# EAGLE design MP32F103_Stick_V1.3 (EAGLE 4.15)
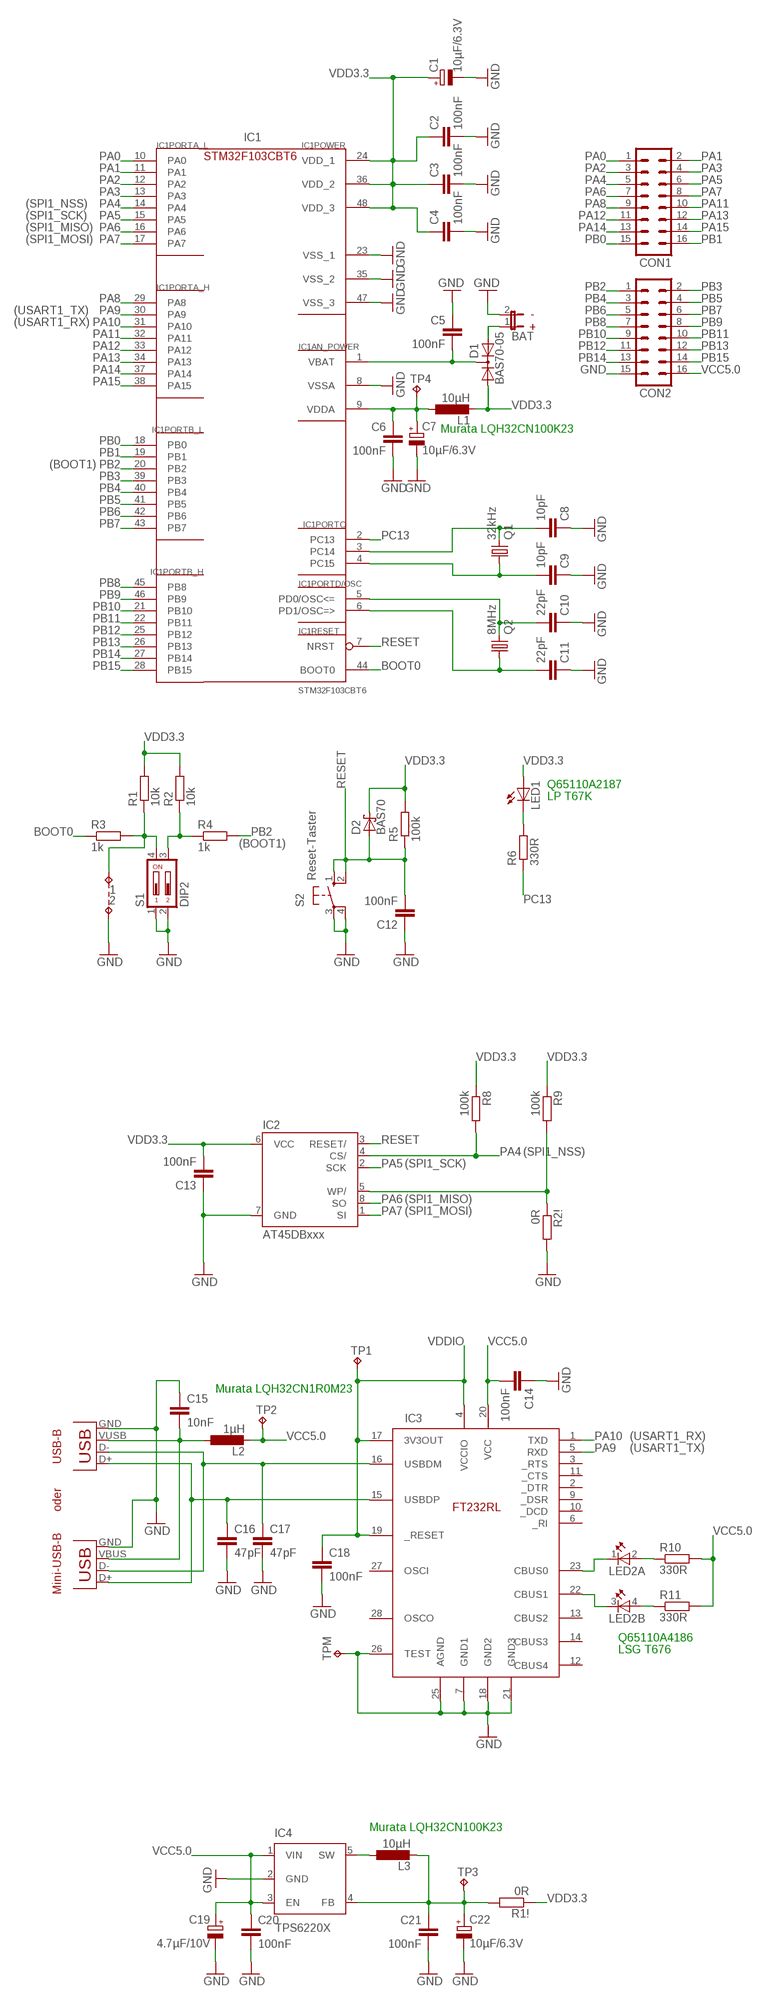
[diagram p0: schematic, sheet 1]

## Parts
1  TP09SQ  [TP09SQ]
2  TP09SQ  [TP09SQ]
BAT  JP1EMP  [JP1_MP]
C1  10µF/6.3V  CPOL-EUA/3216-18R  [A/3216-18R]
C2  100nF  C-EUC0805  [C0805]
C3  100nF  C-EUC0805  [C0805]
C4  100nF  C-EUC0805  [C0805]
C5  100nF  C-EUC0805  [C0805]
C6  100nF  C-EUC0805  [C0805]
C7  10µF/6.3V  CPOL-EUA/3216-18R  [A/3216-18R]
C8  10pF  C-EUC0805K  [C0805K]
C9  10pF  C-EUC0805K  [C0805K]
C10  22pF  C-EUC0805K  [C0805K]
C11  22pF  C-EUC0805K  [C0805K]
C12  100nF  C-EUC0805K  [C0805K]
C13  100nF  C-EUC0805K  [C0805K]
C14  100nF  C-EUC0805K  [C0805K]
C15  10nF  C-EUC0805K  [C0805K]
C16  47pF  C-EUC0805K  [C0805K]
C17  47pF  C-EUC0805K  [C0805K]
C18  100nF  C-EUC0805K  [C0805K]
C19  4.7µF/10V  CPOL-EUA/3216-18R  [A/3216-18R]
C20  100nF  C-EUC0805  [C0805]
C21  100nF  C-EUC0805  [C0805]
C22  10µF/6.3V  CPOL-EUA/3216-18R  [A/3216-18R]
CON1  ML16  [ML16]
CON2  ML16  [ML16]
D1  BAS70-05  [SOT23]
D2  BAS70  [SOT23]
IC1  STM32F103CBT6  STM32F10XCXT6  [TQFP48]
IC2  AT45DBxxx  AT45DB  [SOIC8]
IC3  FT232RL  [SSOP28DB]
IC4  TPS6220X  [SOT23-5L]
L1  10µH  L-EUL1210  [R1210]
L2  1µH  L-EUL1210  [R1210]
L3  10µH  L-EUL1210  [R1210]
LED1  LEDP-LCC-2_MPI  [P-LCC-2-MPI]
LED2  TOPLED-2-MPI  [P-LCC-4-2-MPI]
Q1  32kHz  CRYTALTC26H  [TC26H]
Q2  8MHz  CRYTALHC49U-V  [HC49U-V]
R1  10k  R-EU_R0805  [R0805]
R1!  0R  R-EU_R0805  [R0805]
R2  10k  R-EU_R0805  [R0805]
R2!  0R  R-EU_R0805  [R0805]
R3  1k  R-EU_R0805  [R0805]
R4  1k  R-EU_R0805  [R0805]
R5  100k  R-EU_R0805  [R0805]
R6  330R  R-EU_R0805  [R0805]
R8  100k  R-EU_R0805  [R0805]
R9  100k  R-EU_R0805  [R0805]
R10  330R  R-EU_R0805  [R0805]
R11  330R  R-EU_R0805  [R0805]
S1  DIP2  DS02  [DS-02]
S2  Reset-Taster  10-XX  [B3F-10XX]
TP1  TP09SQ  [TP09SQ]
TP2  TP09SQ  [TP09SQ]
TP3  TP09SQ  [TP09SQ]
TP4  TP09SQ  [TP09SQ]
TPM  TP09SQ  [TP09SQ]
USB1  USB-B-S  [USB-B-SMT]
USB2  USB-MB-S2  [USB-MP-S2]

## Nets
3V3: C21.1 C22.+ IC4.4(FB) L3.2 R1!.2 TP3.TP
BOOT0: IC1.44(RESET:BOOT0) R3.1
D+: C16.1 IC3.15(USBDP) USB1.D+ USB2.D+
D-: C17.1 IC3.16(USBDM) USB1.D- USB2.D-
GND: 2.TP BAT.2 C1.- C2.2 C3.2 C4.2 C5.1 C6.2 C7.- C8.1 C9.1 C10.1 C11.1 C12.1 C13.1 C14.1 C15.1 C16.2 C17.2 C18.2 C19.- C20.2 C21.2 C22.- CON2.15 IC1.8(AN_POWER:VSSA) IC1.23(POWER:VSS_1) IC1.35(POWER:VSS_2) IC1.47(POWER:VSS_3) IC2.7(GND) IC3.7(GND1) IC3.18(GND2) IC3.21(GND3) IC3.25(AGND) IC3.26(TEST) IC4.2(GND) R2!.2 S1.1 S1.2 S2.3(P) S2.4(P1) TPM.TP USB1.GND USB2.GND
N$1: IC4.5(SW) L3.1
N$2: IC3.23(CBUS0) LED2.1(A:C)
N$3: IC3.22(CBUS1) LED2.3(B:C)
N$4: LED2.2(A:A) R10.1
N$5: LED2.4(B:A) R11.1
N$8: BAT.1 D1.2(A2)
N$9: LED1.C R6.2
N$10: 1.TP R1.1 R3.2 S1.4
N$11: R2.1 R4.1 S1.3
N$16: C9.2 IC1.4(PORTC:PC15) Q1.1
N$18: C10.2 IC1.5(PORTD/OSC:PD0/OSC<=) Q2.2
N$19: C11.2 IC1.6(PORTD/OSC:PD1/OSC=>) Q2.1
N$20: C8.2 IC1.3(PORTC:PC14) Q1.2
PA0: CON1.1 IC1.10(PORTA_L:PA0)
PA1: CON1.2 IC1.11(PORTA_L:PA1)
PA2: CON1.3 IC1.12(PORTA_L:PA2)
PA3: CON1.4 IC1.13(PORTA_L:PA3)
PA4: CON1.5 IC1.14(PORTA_L:PA4) IC2.4(CS/) R8.2
PA5: CON1.6 IC1.15(PORTA_L:PA5) IC2.2(SCK)
PA6: CON1.7 IC1.16(PORTA_L:PA6) IC2.8(SO)
PA7: CON1.8 IC1.17(PORTA_L:PA7) IC2.1(SI)
PA8: CON1.9 IC1.29(PORTA_H:PA8)
PA9: IC1.30(PORTA_H:PA9) IC3.5(RXD)
PA10: IC1.31(PORTA_H:PA10) IC3.1(TXD)
PA11: CON1.10 IC1.32(PORTA_H:PA11)
PA12: CON1.11 IC1.33(PORTA_H:PA12)
PA13: CON1.12 IC1.34(PORTA_H:PA13)
PA14: CON1.13 IC1.37(PORTA_H:PA14)
PA15: CON1.14 IC1.38(PORTA_H:PA15)
PB0: CON1.15 IC1.18(PORTB_L:PB0)
PB1: CON1.16 IC1.19(PORTB_L:PB1)
PB2: CON2.1 IC1.20(PORTB_L:PB2) R4.2
PB3: CON2.2 IC1.39(PORTB_L:PB3)
PB4: CON2.3 IC1.40(PORTB_L:PB4)
PB5: CON2.4 IC1.41(PORTB_L:PB5)
PB6: CON2.5 IC1.42(PORTB_L:PB6)
PB7: CON2.6 IC1.43(PORTB_L:PB7)
PB8: CON2.7 IC1.45(PORTB_H:PB8)
PB9: CON2.8 IC1.46(PORTB_H:PB9)
PB10: CON2.9 IC1.21(PORTB_H:PB10)
PB11: CON2.10 IC1.22(PORTB_H:PB11)
PB12: CON2.11 IC1.25(PORTB_H:PB12)
PB13: CON2.12 IC1.26(PORTB_H:PB13)
PB14: CON2.13 IC1.27(PORTB_H:PB14)
PB15: CON2.14 IC1.28(PORTB_H:PB15)
PC13: IC1.2(PORTC:PC13) R6.1
RESET: C12.2 D2.1(A) IC1.7(RESET:NRST) IC2.3(RESET/) R5.1 S2.1(S) S2.2(S1)
VBAT: C5.2 D1.3(C) IC1.1(AN_POWER:VBAT)
VBUS: C15.2 L2.1 USB1.VUSB(VBUS) USB2.VBUS
VCC5.0: C14.2 C19.+ C20.1 CON2.16 IC3.20(VCC) IC4.1(VIN) IC4.3(EN) L2.2 R10.2 R11.2 TP2.TP
VDD3.3: C1.+ C2.1 C3.1 C4.1 C13.2 D1.1(A1) D2.3(C) IC1.24(POWER:VDD_1) IC1.36(POWER:VDD_2) IC1.48(POWER:VDD_3) IC2.6(VCC) L1.2 LED1.A R1!.1 R1.2 R2.2 R5.2 R8.1 R9.1
VDDA: C6.1 C7.+ IC1.9(AN_POWER:VDDA) L1.1 TP4.TP
VDDIO: C18.1 IC3.4(VCCIO) IC3.17(3V3OUT) IC3.19(_RESET) TP1.TP
WP/: IC2.5(WP/) R2!.1 R9.2
Unconnected: IC3.2(_DTR) IC3.3(_RTS) IC3.6(_RI) IC3.9(_DSR) IC3.10(_DCD) IC3.11(_CTS) IC3.12(CBUS4) IC3.13(CBUS2) IC3.14(CBUS3) IC3.27(OSCI) IC3.28(OSCO)

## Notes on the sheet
- IC1
- STM32F103CBT6
- (SPI1_NSS)
- (SPI1_SCK)
- (SPI1_MISO)
- (SPI1_MOSI)
- (USART1_TX)
- -
- (USART1_RX)
- +
- Murata LQH32CN100K23
- (BOOT1)
- Q65110A2187
- LP T67K
- (BOOT1)
- (SPI1_NSS)
- (SPI1_SCK)
- (SPI1_MISO)
- (SPI1_MOSI)
- Murata LQH32CN1R0M23
- (USART1_RX)
- (USART1_TX)
- USB-B
- oder | FT232RL
- Mini-USB-B
- Q65110A4186
- LSG T676
- Murata LQH32CN100K23

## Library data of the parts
1 2 TP1-TP4 TPM = testpad:TP09SQ: TEST PIN
BAT = jumper:JP1E: JUMPER
C1 C7 C19 C22 = rcl:CPOL-EU: POLARIZED CAPACITOR, European symbol
C2-C6 C8-C18 C20 C21 = rcl:C-EU: CAPACITOR, European symbol
CON1 CON2 = con-harting-ml:ML16: HARTING
D1 = diode:BAS70-05: Silicon Schottky Diodes General-purpose diode for high-speed switching
D2 = diode:BAS70: Silicon Schottky Diodes
IC1 = stm32:STM32F10XCXT6: ST STM32F101/103 48pin LQFP
IC2 = atmel:AT45DB*
IC3 = ftdichip:FT232RL: USB UART 4th Generation USB UART (USB <-> Serial) Controller
IC4 = texas_MPi:TPS6220X
L1-L3 = rcl:L-EU: INDUCTOR, European symbol
LED1 = led:LED: LED
LED2 = led:TOPLED-2-: Multi TOPLED® (two color) LG T672, LP T672 LSY T67B LSW T67C LSY T675 LSY T676 LSG T677 LSG T770 Source: http://www.osram.convergy.de/
Q1 Q2 = crystal:CRYTAL: CRYSTAL
R1 R1! R2 R2! R3-R6 R8-R11 = rcl:R-EU_: RESISTOR, European symbol
S1 = switch-dil:DS02: DIL/CODE SWITCH
S2 = switch-omron:10-XX: OMRON SWITCH
USB1 USB2 = con-usb:USB: USB Connectors

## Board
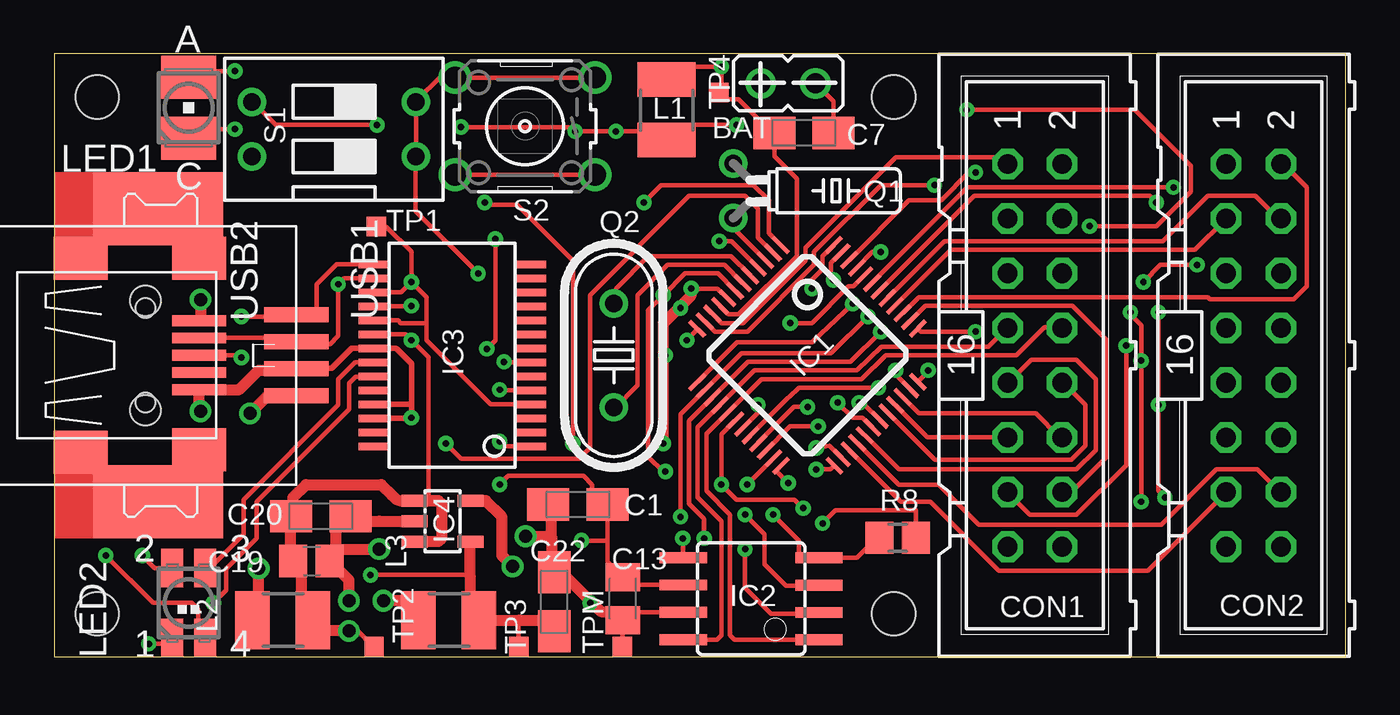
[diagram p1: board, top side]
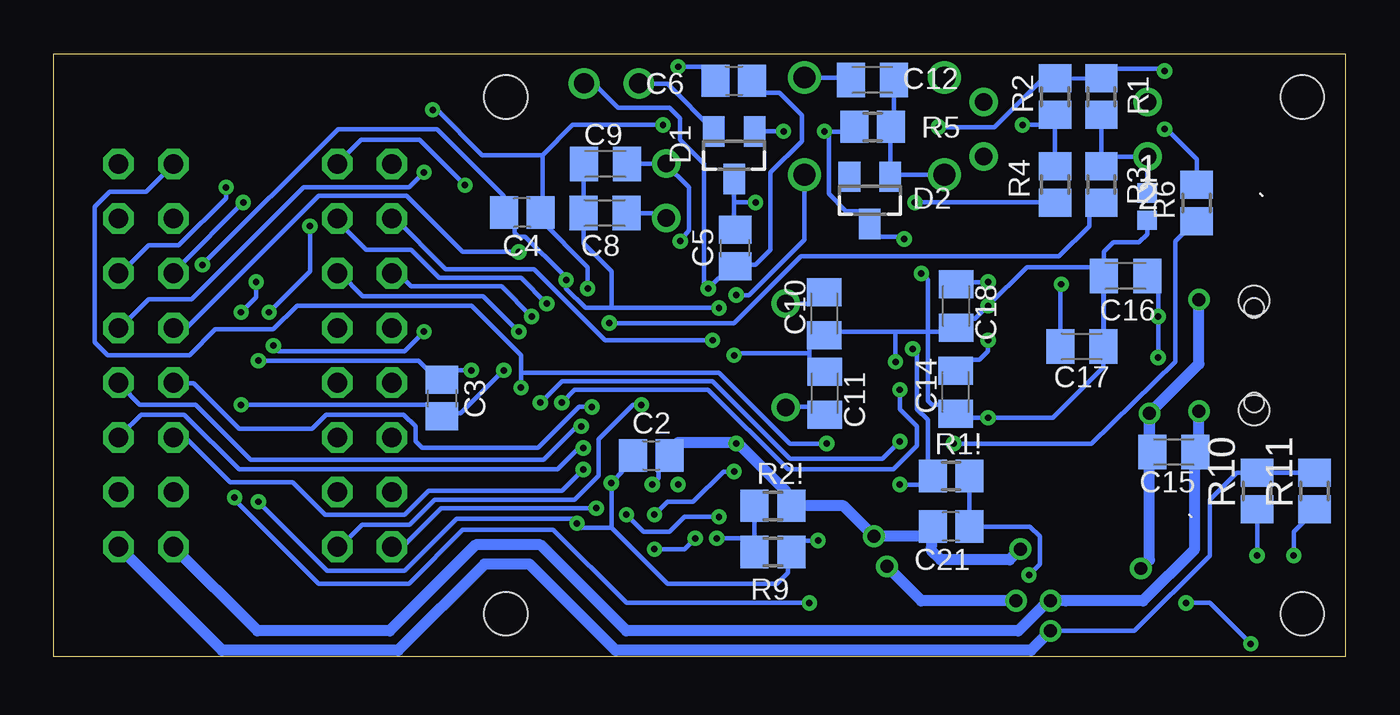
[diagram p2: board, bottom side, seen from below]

Size 60 x 28 mm. Coordinates in mm from the lower left corner, seen from the top.
Outline: 0,0 60,0 60,28 0,28 0,0
Copper layers (1*16): Top 0.035mm / dielectric 1.5mm / Bottom 0.035mm
Design rules "default": minimum track width 5mil, minimum drill 10mil, track to track 5mil, track to pad 8mil, pad to pad 8mil, via to via 8mil, smd to smd 8mil, copper to edge 5mil, drill to drill 8mil, minimum pad ring 10mil, minimum via ring 8mil, stop-mask expansion 4mil, vias tented up to drill 0mil, thermal gap 10mil
Holes 2 mm at 2,2 2,26 39,26 39,2
tRestrict: area 0,24 to 4,28; area 0,0 to 4,4; area 37,0 to 41,4; area 37,24 to 41,28
bRestrict: area 0,24 to 4,28; area 0,0 to 4,4; area 37,24 to 41,28; area 37,0 to 41,4

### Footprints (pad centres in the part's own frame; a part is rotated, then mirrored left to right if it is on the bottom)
TP09SQ = smd 0.9 x 0.9: TP 0,0
JP1_MP = drill 0.914 round: 1 0,-1.27; 2 0,1.27
A/3216-18R = smd 1.95 x 1.5: + 1.375,0; - -1.375,0
C0805 = smd 1.3 x 1.5: 1 -0.85,0; 2 0.85,0
C0805K = smd 1.3 x 1.6: 1 -1,0; 2 1,0
ML16 = drill 0.914 octagon: 1 -8.89,-1.27; 2 -8.89,1.27; 3 -6.35,-1.27; 4 -6.35,1.27; 5 -3.81,-1.27; 6 -3.81,1.27; 7 -1.27,-1.27; 8 -1.27,1.27; 9 1.27,-1.27; 10 1.27,1.27; 11 3.81,-1.27; 12 3.81,1.27; 13 6.35,-1.27; 14 6.35,1.27; 15 8.89,-1.27; 16 8.89,1.27
SOT23 = smd 1 x 1.4: 1 -0.95,-1.1; 2 0.95,-1.1; 3 0,1.1
TQFP48 = smd 0.2 x 1: 1 -2.75,-4.5; 2 -2.25,-4.5; 3 -1.75,-4.5; 4 -1.25,-4.5; 5 -0.75,-4.5; 6 -0.25,-4.5; 7 0.25,-4.5; 8 0.75,-4.5; 9 1.25,-4.5; 10 1.75,-4.5; 11 2.25,-4.5; 12 2.75,-4.5; 25 2.75,4.5; 26 2.25,4.5; 27 1.75,4.5; 28 1.25,4.5; 29 0.75,4.5; 30 0.25,4.5; 31 -0.25,4.5; 32 -0.75,4.5; 33 -1.25,4.5; 34 -1.75,4.5; 35 -2.25,4.5; 36 -2.75,4.5 | smd 1 x 0.2: 13 4.5,-2.75; 14 4.5,-2.25; 15 4.5,-1.75; 16 4.5,-1.25; 17 4.5,-0.75; 18 4.5,-0.25; 19 4.5,0.25; 20 4.5,0.75; 21 4.5,1.25; 22 4.5,1.75; 23 4.5,2.25; 24 4.5,2.75; 37 -4.5,2.75; 38 -4.5,2.25; 39 -4.5,1.75; 40 -4.5,1.25; 41 -4.5,0.75; 42 -4.5,0.25; 43 -4.5,-0.25; 44 -4.5,-0.75; 45 -4.5,-1.25; 46 -4.5,-1.75; 47 -4.5,-2.25; 48 -4.5,-2.75
SOIC8 = smd 0.5 x 2.2: 1 -1.905,-3.154; 2 -0.645,-3.154; 3 0.625,-3.154; 4 1.895,-3.154; 5 1.905,3.154; 6 0.635,3.154; 7 -0.635,3.154; 8 -1.905,3.154
SSOP28DB = smd 0.348 x 1.397: 1 -4.225,-3.656; 2 -3.575,-3.656; 3 -2.925,-3.656; 4 -2.275,-3.656; 5 -1.625,-3.656; 6 -0.975,-3.656; 7 -0.325,-3.656; 8 0.325,-3.656; 9 0.975,-3.656; 10 1.625,-3.656; 11 2.275,-3.656; 12 2.925,-3.656; 13 3.575,-3.656; 14 4.225,-3.656; 15 4.225,3.656; 16 3.575,3.656; 17 2.925,3.656; 18 2.275,3.656; 19 1.625,3.656; 20 0.975,3.656; 21 0.325,3.656; 22 -0.325,3.656; 23 -0.975,3.656; 24 -1.625,3.656; 25 -2.275,3.656; 26 -2.925,3.656; 27 -3.575,3.656; 28 -4.225,3.656
SOT23-5L = smd 1.2 x 0.55: 1 -1.3,0.95; 2 -1.3,0; 3 -1.3,-0.95; 4 1.3,-0.95; 5 1.3,0.95
R1210 = smd 1.6 x 2.7: 1 -1.4,0; 2 1.4,0
P-LCC-2-MPI = smd 2.54 x 2: A 0,1.415; C 0,-1.415
P-LCC-4-2-MPI = smd 1.016 x 1.778: 1 -0.77,-1.619; 2 -0.77,1.619; 3 0.77,1.619; 4 0.77,-1.619
TC26H = drill 0.813 round: 1 -1.27,0; 2 1.27,0
HC49U-V = drill 0.813 round: 1 -2.413,0; 2 2.413,0
R0805 = smd 1.3 x 1.5: 1 -0.85,0; 2 0.85,0
DS-02 = drill 0.813 round: 1 -1.27,-3.81; 2 1.27,-3.81; 3 1.27,3.81; 4 -1.27,3.81
B3F-10XX = drill 1.016 round: 1 -3.251,2.261; 2 3.251,2.261; 3 -3.251,-2.261; 4 3.251,-2.261
USB-B-SMT = smd 6.04 x 3.4: 5 0.58,6.8; 6 0.58,-6.8 | smd 3 x 0.7: D+ 7,1.875; D- 7,0.625; GND 7,-0.625; VUSB 7,-1.875 | hole 1.4: 0,2.529; 0,-2.555
USB-MP-S2 = smd 2.5 x 0.5: D+ 2.487,0.005; D- 2.487,0.805; GND 2.487,-1.595; ID 2.487,-0.795; VBUS 2.487,1.605 | smd 2.5 x 2: P$1 -3.013,-4.495; P$2 -3.013,4.505; P$3 2.487,-4.395; P$4 2.487,4.505 | hole 0.9: -0.013,2.205; -0.013,-2.195

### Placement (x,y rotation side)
1  9.21,21.54 0 bottom
2  9.21,20.27 0 bottom
BAT  34.1,26.63 270 top
C1  24.33,7.07 0 top
C2  32.25,9.35 0 bottom
C3  41.97,12.01 270 bottom
C4  38.24,20.63 180 bottom
C5  28.35,18.98 90 bottom
C6  28.41,26.75 0 bottom
C7  34.83,24.33 180 top
C8  34.4,20.61 0 bottom
C9  34.38,22.89 0 bottom
C10  24.21,15.94 90 bottom
C11  24.19,12.24 270 bottom
C12  21.97,26.79 0 bottom
C13  26.41,2.7 90 top
C14  18.11,12.29 90 bottom
C15  7.97,9.51 180 bottom
C16  10.21,17.69 180 bottom
C17  12.25,14.41 0 bottom
C18  18.09,16.29 270 bottom
C19  12.39,6.53 180 top
C20  11.96,4.45 0 top
C21  18.32,6.05 180 bottom
C22  23.23,2.55 270 top
CON1  45.56,14 270 top
CON2  55.72,14 270 top
D1  28.4,23.29 180 bottom
D2  22.09,21.2 180 bottom
IC1  35,14 225.1 top
IC2  32.38,2.7 90 top
IC3  18.5,14 90 top
IC4  18.04,6.3 0 top
L1  28.45,25.4 270 top
L2  10.62,1.7 0 top
L3  18.33,1.7 0 top
LED1  6.25,25.5 0 top
LED2  6.25,2.5 0 top
Q1  31.56,21.64 270 top
Q2  26,14 90 top
R1  11.34,26.01 90 bottom
R1!  18.32,8.39 0 bottom
R2  13.49,26.01 90 bottom
R2!  26.59,7.01 0 bottom
R3  11.34,21.93 90 bottom
R4  13.49,21.93 270 bottom
R5  21.96,24.61 180 bottom
R6  6.91,21.08 90 bottom
R8  39.19,5.53 180 top
R9  26.59,4.87 180 bottom
R10  4.11,7.7 90 bottom
R11  1.43,7.7 90 bottom
S1  13,24.5 90 top
S2  21.88,24.64 180 top
TP1  14.97,19.98 0 top
TP2  14.87,0.48 0 top
TP3  21.58,0.48 0 top
TP4  30.87,26.21 0 top
TPM  26.4,0.48 0 top
USB1  4.25,14 0 top
USB2  4.25,14 0 top

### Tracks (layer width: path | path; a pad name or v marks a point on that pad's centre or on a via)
3V3  (via drill 0.3)
  Top 0.2: 19.33,3.7 19.3,3.8 v14.7,3.8 | TP3.TP 21.58,1.68 21.6,1.7
  Top 0.5: IC4.4 19.34,5.24 19.3,5.2 19.33,5.17 19.33,3.7 19.33,2.63 19.3,2.6 L3.2 19.7,1.7 21.6,1.7 23.1,1.7 23.18,1.62 23.18,1.23 23.2,1.2 C22.+
  Bottom 0.2: R1!.2 17.47,6.03 17.5,6 17.52,6.02 C21.1 14.65,6.05 14.2,5.6 14.2,4.3 v14.7,3.8
BOOT0  (via drill 0.3)
  Top 0.2: IC1.44 37.13,17.2 36.9,17.2 35.2,15.5 v34.2,15.5
  Bottom 0.2: v34.2,15.5 29.2,15.5 28.4,15.5 25.3,18.6 13.3,18.6 11.9,20 11.9,20.8 11.5,20.8 11.3,21 11.33,21.03 R3.1
D+  (via drill 0.3)
  Top 0.2: v8.7,15.8 11.2,15.8 | 11.2,15.8 11.5,15.8 | 11.5,15.8 12.2,15.8 | 12.2,15.8 12.6,15.8 | IC3.15 13.12,18.23 12.2,17.3 12.2,15.8 | 11.5,15.8 11.43,15.88 USB1.D+ | 11.2,15.8 11.5,15.8 | v8.7,13.9 8.7,14 8.7,14.01 USB2.D+
  Top 0.305: 11.2,15.8 11.22,15.78 11.2,15.8
  Bottom 0.2: v8.7,13.9 v8.7,15.8 8.7,17.1 9.2,17.6 9.21,17.51 C16.1
D-  (via drill 0.3)
  Top 0.2: IC3.16 13.68,17.57 13.47,17.57 v13.2,17.3 13.2,14.9 12.82,14.53 11.18,14.53 11.1,14.6 11.12,14.62 USB1.D- | USB1.D- 11.38,14.62 11.4,14.6 11.32,14.53 11.12,14.53 | USB1.D- 11.22,14.62 11.2,14.6 10.99,14.8 USB2.D-
  Top 0.305: 11.12,14.53 11.1,14.5 11.01,14.79
  Bottom 0.2: C17.1 13.25,17.25 v13.2,17.3
GND  (via drill 0.3, 0.6)
  Top 0.2: IC1.23 v32.2,8.01 v32.2,8 | IC1.35 39.1,13.09 v39.1,13.3 | IC3.18 16.23,16.27 v16.6,16.3 | IC1.47 36.1,18.29 36.1,17.7 v36.2,17.5 | IC1.8 30.83,17.1 v29.6,17.1 29.6,16.8 | v53.1,18.2 51.4,18.2 v50.6,17.4 | v51.3,16 51.3,12.3 v51.3,11.7 51.3,7.7 v51.6,7.4 | C7.- 36.2,25.8 35.4,26.6 BAT.2 | S2.3 25.1,26.9 S2.4 18.6,26.9 17.9,26.9 16.87,25.87 S1.2 16.81,23.41 16.8,23.2 | 16.8,23.2 16.77,23.23 S1.1 16.81,23.21 16.8,23.2 | IC2.7 26.96,2.06 26.5,1.6 26.45,1.55 C13.1 26.41,1.61 26.4,1.6 TPM.TP | IC3.7 20.93,13.68 v20.9,13.7 | 14.82,11.07 14.8,11.1 | 14.8,11.7 14.82,11.72 IC3.25 | v24.9,2.5 24.8,2.6 24.8,2.7 | v28.3,9.9 28.3,10 | v19.7,17.8 16.8,20.7 16.8,23.1 16.8,23.2 | 11.43,13.27 11.3,13.4 11.28,13.38 USB1.GND 11.25,13.35 11.2,13.3 11.18,13.28
  Top 0.254: USB1.GND 11.38,13.38 11.4,13.4 12.9,13.4 13.82,14.32 IC3.21 15.88,14.32 15.9,14.3 16.6,13.6 16.6,11.7 | 16.6,11.7 v16.6,11.1 16.57,11.07 IC3.26 14.82,11.07 | IC3.25 16.57,11.72 16.6,11.7 | 14.82,11.07 14.8,11.1 14.82,11.07
  Top 0.5: 6.75,11.45 v6.8,11.4 6.74,11.46 USB2.GND 8.61,12.4 9.5,13.3 10.5,13.3 11.1,13.3 11.2,13.4 11.22,13.38 USB1.GND | 13.1,5 13.1,4.5 12.86,4.5 C20.2 13.7,3.56 v13.7,2.6 | 13.1,5 13.1,5.87 C19.- 13.99,6.3 14,6.3 15.1,6.3 IC4.2 | C1.- 23.02,7 23.1,7 23.1,5.6 | C22.- 23.1,4.05 | C13.1 26.01,2.1 25.4,2.1 24.8,2.7 23.3,4.2 23.3,4 C22.- | v21.9,5.6 23.1,5.6 | C22.- 23.23,4.17 23.1,4.3 23.1,5.6 | 29.6,16.8 28.3,15.5 28.3,10 | 13.1,5 v15.1,5
  Bottom 0.2: v39.1,13.3 41.1,11.3 41.9,11.3 41.93,11.1 C3.2 42.01,11.2 42.4,11.7 43.4,11.7 v51.3,11.7 | 38.6,20.5 38.96,20.5 C4.2 39.09,20.69 39.1,20.7 39.1,21.4 42.2,24.5 46.8,24.5 v53.1,18.2 | 38.6,20.5 38.6,19.7 38.4,19.5 38.1,19.5 36.4,17.8 v36.2,17.5 36.2,17.1 35.3,16.2 34.1,16.2 | C9.1 35.59,23.1 | 38.6,20.5 38.6,20.9 | 35.4,22.91 35.4,23.1 C8.1 35.4,19.2 34.1,17.9 34.1,16.2 | 35.4,22.91 C9.1 | 35.4,22.91 35.4,23.2 | 35.4,22.91 C9.1 | v50.6,17.4 50.6,16.7 v51.3,16 | C11.1 24.8,13.4 24.9,13.5 24.9,14.1 | 24.9,14.1 24.9,14.6 24.2,14.8 C10.1 24.21,14.81 24.1,14.7 23.8,15.1 20.9,15.1 | v32.2,8 31.9,8.3 31.9,9 C2.2 31.4,9.6 31,9.95 | 25.1,26.9 S2.3 23.1,26.9 23,26.8 22.99,26.79 C12.1 | 35.3,23.3 35.38,23.22 C9.1 | BAT.2 35.33,26.63 35.3,26.6 34.9,26.6 33.8,25.5 31.4,25.5 30.9,25 30.9,24.4 30.9,24 29.8,22.9 29.8,17.3 v29.6,17.1 28.6,18.1 28.57,18.13 C5.1 28.33,18.13 28.3,18.1 28.2,18.2 27.4,18.2 26.7,18.9 26.7,22.5 25.25,23.95 25.25,25.15 26.3,26.2 27.4,26.2 27.4,26.5 27.6,26.7 C6.2 | C17.2 11.25,14.45 11.2,14.5 11.21,14.51 C16.2 11.21,17.72 11.22,17.73 11.21,17.74 11.21,18.82 10.78,19.25 9.59,19.25 9.21,19.63 2.TP | R2!.2 25.79,7.01 25.8,7 26,6.8 | 54.4,5.1 CON2.15 | 19.4,15.1 18.4,15.1 18.31,15.29 C18.2 18.09,15.31 18,15.4 17.7,15.7 17.2,15.7 v16.6,16.3 14.8,18.1 11.4,18.1 11.25,18.05 C17.2 | 19.4,15.1 19.4,11.9 19.2,11.7 18.5,11.7 C14.1 18.01,11.29 18,11.3 17.8,11.1 v16.6,11.1 13.6,11.1 11.25,13.45 C17.2 | 19.4,15.1 20.9,15.1 | 20.9,15.1 v20.9,13.7 | v24.9,2.5 33.4,2.5 36.8,5.9 41,5.9 43.5,3.4 47.7,3.4 49.9,5.6 51.6,7.3 v51.6,7.4 | 19.4,15.1 19.4,17.5 v19.7,17.8
  Bottom 0.2: 34.1,16.2 v29.1,16.2 | v28.3,9.9 28.3,10 28.25,9.95 | 24.9,14.1 28.3,14.1 v28.4,14
  Bottom 0.5: v6.8,11.4 6.8,9.6 7,9.4 6.97,9.43 C15.1 7,9.54 7,9.6 7,5 9.4,2.6 13,2.6 | 31,9.95 28.25,9.95 26,7.7 26,6.8 | CON2.15 50.54,1.2 44.4,1.2 40.4,5.2 37.4,5.2 33.4,1.2 15.2,1.2 13.8,2.6 v13.7,2.6 | 13,2.6 v13.7,2.6 | 13,2.6 v13.7,2.6 | v15.1,5 15.6,4.5 18.8,4.5 19.22,4.92 C21.2 19.25,6.05 19.3,6 19.5,5.8 19.5,5.6 v21.9,5.6 23.31,7.01 R2!.2
N$1  (via drill 0.6)
  Top 0.5: IC4.5 20.05,7.25 20.8,6.5 20.8,4.7 v21.3,4.2 | L3.1 16.93,1.73 17,1.7 16.1,2.6 v15.3,2.6
  Bottom 0.5: v21.3,4.2 19.7,2.6 v15.3,2.6
N$2  (via drill 0.3)
  Top 0.2: v7.4,2.5 8,3.1 8,4.1 9.4,5.5 9.4,7.2 13.7,11.5 13.7,12.7 14,13 14.8,13 14.82,13.03 IC3.23 | LED2.1 5.48,0.62 5.5,0.6 v4.4,0.6
  Bottom 0.2: v7.4,2.5 6.3,2.5 v4.4,0.6
N$3
  Top 0.2: LED2.3 7.22,4.12 8.8,5.7 8.8,7.3 13.2,11.7 13.2,12.9 13.97,13.68 IC3.22
N$4  (via drill 0.3)
  Top 0.2: LED2.2 4.68,4.12 v4.1,4.7
  Bottom 0.2: R10.1 4.11,6.81 4.1,6.8 v4.1,4.7
N$5  (via drill 0.3)
  Top 0.2: v2.4,4.7 4.6,2.5 6.4,2.5 6.7,2.2 6.7,1.2 LED2.4
  Bottom 0.2: R11.1 1.43,6.83 1.4,6.8 2.4,5.8 v2.4,4.7
N$8
  Bottom 0.2: 32.87,26.63 BAT.1 32.87,26.63 | D1.2 29.29,24.39 31.5,26.6 32.9,26.6 32.87,26.63
N$9  (via drill 0.3)
  Top 0.2: 5.7,24.7 5.8,24.6 5.9,24.5 6.3,24.5 v8.4,24.5
  Top 0.254: LED1.C 6.24,24.16 5.9,24.5 6.3,24.1 6.3,24.5
  Bottom 0.2: R6.2 6.91,23.11 8.3,24.5 8.37,24.53 v8.4,24.5
N$10
  Bottom 0.2: 11.3,22.8 R3.2 11.3,22.8 | R1.1 11.34,22.84 11.3,22.8 | 11.3,22.8 11.2,22.9 10.87,23.23 S1.4 9.2,23.21 9.21,23.2 1.TP
N$11  (via drill 0.3)
  Top 0.2: S1.3 9.23,25.77 9.3,25.7 10.3,24.7 v15,24.7
  Bottom 0.2: R4.1 13.47,22.87 13.5,22.9 13.49,22.91 R2.1 13.64,25.16 14.1,24.7 v15,24.7
N$16  (via drill 0.3)
  Top 0.2: IC1.4 31.46,19.3 v30.9,19.3
  Bottom 0.2: C9.2 31.6,22.9 | 31.6,22.9 Q1.1 | Q1.1 | v30.9,19.3 30.5,19.8 30.5,21.8 31.6,22.9 | 31.6,22.9 Q1.1
N$18
  Top 0.2: IC1.5 31.45,18.6 27.6,18.6 26.1,17.1 26.1,16.4 26.01,16.4 Q2.2
  Bottom 0.2: Q2.2 25.99,16.4 25.9,16.4 24.75,16.4 C10.2
N$19
  Top 0.2: IC1.6 31.14,18.2 28.5,18.2 27.1,16.8 27.1,12.6 26,11.5 Q2.1
  Bottom 0.2: Q2.1 25.99,11.6 25.9,11.6 24.55,11.6 C11.2
N$20
  Top 0.2: Q1.2 31.6,20.33 31.6,20.3 31.6,19.86 IC1.3
  Bottom 0.2: Q1.2 31.79,20.6 32,20.6 C8.2
PA0
  Top 0.2: IC1.10 31.01,15.5 32,15.5 34.9,18.4 34.9,19 39.1,23.2 44,23.2 CON1.1
PA1  (via drill 0.3)
  Top 0.2: v40.9,21.9 38.4,21.9 35.3,18.8 35.3,18.2 32.2,15.1 30.7,15.1 30.2,15.6 30.21,15.6 IC1.11
  Bottom 0.2: CON1.2 45.72,24 43,24 41.4,22.4 v40.9,21.9
PA2  (via drill 0.3)
  Top 0.2: 29.9,15.2 | IC1.12 29.9,15.2 | 29.9,15.2 v29.4,14.7
  Bottom 0.2: CON1.3 44.3,20.4 44.2,20.4 41.8,18 37.7,18 34.4,14.7 v29.4,14.7
PA3  (via drill 0.3)
  Top 0.2: IC1.13 31.72,14.6 34.6,14.6 | 34.6,14.6 35.22,14.6 | 34.6,14.6 35.22,14.6 | 34.6,14.6 35.22,14.6 | 35.22,14.6 35.2,14.6 v37.1,16.4
  Bottom 0.2: v37.1,16.4 38.3,17.6 42.1,17.6 43.4,18.9 45.5,18.9 46.8,20.2 46.8,20.3 46.8,20.32 CON1.4
PA4  (via drill 0.3)
  Top 0.2: v37.8,15.8 36.1,14.1 34.73,14.1 34.7,14.1 31.93,14.1 30.28,12.45 IC1.14 29.1,11.27 29.1,7.6 v29.1,6.5 | R8.2 38.34,5.56 38.3,5.6 37.3,4.59 IC2.4 35.59,4.59 35.6,4.6 34.6,4.6 34.6,5.4 v33.4,6.6
  Bottom 0.2: v37.8,15.8 39.2,17.2 43.4,17.2 44,17.8 CON1.5 | v29.1,6.5 30.7,6.5 31.4,5.8 32.6,5.8 v33.4,6.6
PA5  (via drill 0.3)
  Top 0.2: v38.4,15.1 37,13.7 35.04,13.7 35,13.7 32.24,13.7 IC1.15 29.5,10.96 29.5,7.1 30.2,6.4 v30.2,5.5 | v32.1,5 32.1,3.2 33.3,2 35.5,2 35.53,2.03 IC2.2
  Bottom 0.2: v38.4,15.1 40.05,16.75 45.65,16.75 46.7,17.8 46.8,17.8 CON1.6 | v32.1,5 30.7,5 v30.2,5.5
PA6
  Top 0.2: CON1.7 44.26,15.3 44.2,15.3 44.2,15.2 43.4,14.4 38.44,14.4 37.3,13.3 32.54,13.3 IC1.16 29.9,10.66 29.9,7.6 29.9,7.4 31,6.3 31,1 30.8,0.8 IC2.8
PA7
  Top 0.2: CON1.8 46.8,15.3 46,15.3 44.7,14 38.65,14 37.5,12.9 32.85,12.9 IC1.17 30.3,10.35 30.3,7.7 31.4,6.6 31.4,1 31.61,0.8 IC2.1
PA8
  Top 0.2: IC1.29 39.25,8.7 47.5,8.7 48.4,9.6 48.4,12.9 47.5,13.8 45.4,13.8 44.3,12.7 CON1.9
PA9  (via drill 0.3)
  Top 0.2: IC1.30 37.56,11.1 37.1,11.1 v36.4,11.8 | 20.8,12.4 v20.7,12.4 20.8,12.4 | 20.8,12.4 20.9,12.4 | IC3.5 20.82,12.38 20.8,12.4
  Bottom 0.2: v36.4,11.8 35.8,12.4 29.6,12.4 25.9,8.7 21,8.7 19.9,9.8 19.9,10.7 20.7,11.5 v20.7,12.4
PA10  (via drill 0.3)
  Top 0.2: IC1.31 37.7,11.66 v37.4,11.8 | 20.9,9.8 v20.7,10 20.93,9.78 IC3.1
  Bottom 0.2: v37.4,11.8 36.4,12.8 29.4,12.8 25.8,9.2 21.5,9.2 v20.7,10
PA11
  Top 0.2: IC1.32 40.92,9.15 47.25,9.15 47.9,9.8 47.9,11.7 46.9,12.7 46.86,12.7 CON1.10
PA12
  Top 0.2: CON1.11 40.58,10.2 IC1.33
PA13
  Top 0.2: IC1.34 40.19,11.3 45.6,11.3 46.7,10.2 CON1.12
PA14  (via drill 0.3)
  Top 0.2: IC1.37 40.28,15.1 v42.8,15.1 | CON1.13 45.34,6.6 47.5,6.6 49.8,8.9 v49.8,14.45
  Bottom 0.2: v42.8,15.1 43.7,14.2 49.55,14.2 v49.8,14.45
PA15
  Top 0.2: IC1.38 40.47,16.3 47.3,16.3 48.9,14.7 48.9,9.3 47.2,7.6 46.8,7.6 46.8,7.62 CON1.14
PB0  (via drill 0.3)
  Top 0.2: IC1.18 31,10.34 v31,8 31.7,7.3 34.4,7.3 v34.8,6.9
  Bottom 0.2: v34.8,6.9 42,6.9 43.8,5.1 44.2,5.1 CON1.15
PB1  (via drill 0.3)
  Top 0.2: IC1.19 32.7,11.34 32.7,11.6 v32.7,11.7
  Bottom 0.2: CON1.16 46.7,5.1 45.67,6.13 43.47,6.13 42.3,7.3 35.8,7.3 34.7,8.4 34.7,10.1 33.1,11.7 v32.7,11.7
PB2  (via drill 0.3)
  Top 0.2: IC1.20 34,11.93 34.5,12.4 34.6,12.5 v38.3,12.5 | v24.1,9.9 24.1,18.4 21.5,21 20.1,21 v20,21.1
  Bottom 0.2: 38.3,13.2 38.3,14 | 38.3,13.2 v38.3,12.5 38.2,12.5 | 38.3,14 38.35,14.05 | 38.35,14.05 40.6,16.3 48.7,16.3 49.8,15.2 52.5,15.2 53.7,14 57.5,14 58.1,14.6 58.1,20.9 57.4,21.6 56.8,21.6 55.7,21.6 54.5,22.8 54.5,22.84 CON2.1 | v24.1,9.9 25.8,9.9 29.1,13.2 38.3,13.2 | 38.3,14 38.35,14.05 | R4.2 13.5,21.1 v20,21.1
PB3
  Top 0.2: IC1.39 40.16,16.7 53.6,16.7 53.7,16.6 57.6,16.6 58.2,17.2 58.2,21.8 57.1,22.9 CON2.2
PB4
  Top 0.2: IC1.40 41.66,18.9 53,18.9 54.4,20.3 CON2.3
PB5
  Top 0.2: IC1.41 41.35,19.3 51.5,19.3 53.6,21.4 55.8,21.4 56.8,20.4 56.94,20.4 CON2.4
PB6  (via drill 0.3)
  Top 0.2: IC1.42 42.74,21.4 50.9,21.4 v51.2,21.1
  Bottom 0.2: CON2.5 54.4,17.8 54.2,18.1 v51.2,21.1
PB7  (via drill 0.3)
  Top 0.2: IC1.43 42.44,21.8 v52,21.8
  Bottom 0.2: v52,21.8 52,21.3 54.2,19.1 55.6,19.1 56.9,17.8 CON2.6
PB8  (via drill 0.3)
  Top 0.2: IC1.45 38.02,18.8 v38.4,18.8
  Bottom 0.2: 54.5,15.3 54.48,15.3 | 54.48,15.3 CON2.7 54.48,15.3 | v38.4,18.8 41,18.8 43.6,21.4 47.7,21.4 53.8,15.3 54.5,15.3 | 54.5,15.3 54.48,15.3
PB9  (via drill 0.3)
  Top 0.2: IC1.46 39.71,21.2 41.21,21.2 42.5,22.5 v42.8,22.5
  Bottom 0.2: CON2.8 56.96,15.3 56.9,15.3 55.6,16.6 53.6,16.6 48.4,21.8 43.5,21.8 v42.8,22.5
PB10  (via drill 0.3)
  Top 0.2: IC1.21 34.38,11.6 v35,11.6
  Bottom 0.2: v35,11.6 35.6,11.6 37.5,9.7 42.9,9.7 43.2,10 43.2,10.7 43.75,11.25 47.35,11.25 48,10.6 51.4,10.6 53.5,12.7 54.4,12.7 54.42,12.7 CON2.9
PB11  (via drill 0.3)
  Top 0.2: IC1.22 34.19,10.7 v35.5,10.7
  Bottom 0.2: v35.5,10.7 35.7,10.7 | v35.5,10.7 35.7,10.7 | v35.5,10.7 35.7,10.7 | 35.7,10.7 37.25,9.15 50.85,9.15 53.4,11.7 56,11.7 56.9,12.6 56.9,12.7 56.96,12.7 CON2.10
PB12  (via drill 0.3)
  Top 0.2: IC1.25 36.07,8.7 v35.4,8.7
  Bottom 0.2: v35.4,8.7 36.4,7.7 42.6,7.7 43.7,6.6 47.4,6.6 48.9,8.1 51.8,8.1 53.8,10.1 54.5,10.1 54.5,10.14 CON2.11
PB13  (via drill 0.3)
  Top 0.2: IC1.26 36.03,9.8 v35.4,9.7
  Bottom 0.2: v35.4,9.7 35.6,9.7 36.6,8.7 51.4,8.7 53.95,11.25 55.95,11.25 56.9,10.3 CON2.12
PB14
  Top 0.2: IC1.27 39.34,7.2 40.7,7.2 43.9,4 50.8,4 54.4,7.6 CON2.13
PB15
  Top 0.2: IC1.28 39.24,8 41.1,8 42.97,6.13 51.42,6.13 51.43,6.13 54,8.7 55.9,8.7 56.9,7.7 56.95,7.65 CON2.14
PC13  (via drill 0.3)
  Top 0.2: IC1.2 32.7,19.47 32.7,20.8 32.1,21.4 29.5,21.4 24.9,16.8 24.9,9.7 24.4,9.2 23.7,9.2 18.9,9.2 v18.2,9.9
  Bottom 0.2: v18.2,9.9 17.9,9.9 11.8,9.9 7.9,13.7 7.9,19.3 6.9,20.3 6.91,20.29 R6.1
RESET  (via drill 0.3)
  Top 0.2: IC1.7 30.84,17.8 29.3,17.8 v28.3,16.8 27.6,16.1 27.6,9.3 28.3,8.6 v28.4,8.6 | S2.2 18.6,22.4 S2.2 | S2.2 | S2.1 S2.2 | 35.6,3.4 IC2.3 35.51,3.3 34,3.3 33,4.3 33,5.7 v32.1,6.6
  Bottom 0.2: S2.1 25.13,19.37 27.7,16.8 v28.3,16.8 | C12.2 20.97,24.93 21.1,24.8 21.11,24.79 R5.1 21.19,24.61 21.3,24.5 21.14,24.34 D2.1 21.14,22.34 21.2,22.4 21.18,22.38 S2.2 | v28.4,8.6 28.9,8.6 30.3,7.2 31.5,7.2 v32.1,6.6
VBAT  (via drill 0.3)
  Top 0.2: IC1.1 33.2,19.68 33.2,21.2 32.5,21.9 28.2,21.9 v27.4,21.1
  Bottom 0.2: C5.2 28.37,19.83 28.4,19.8 28.4,21.1 | 28.4,21.1 D1.3 | 28.4,21.1 v27.4,21.1
VBUS  (via drill 0.6)
  Top 0.2: 11.22,12.03 11.3,12.1 11.28,12.12 USB1.VUSB | 6.8,15.7 | 6.81,15.7 6.8,15.7 | USB2.VBUS 6.74,15.64 6.8,15.7
  Top 0.5: v6.8,16.59 6.81,15.7 6.81,15.67 | v9.1,11.3 10,12.2 11.4,12.2 11.22,12.03 | L2.1 9.5,1.99 v9.5,4.1
  Bottom 0.5: v6.8,16.59 6.8,13.6 v9.1,11.3 | C15.2 8.91,9.51 8.9,9.5 9.1,9.7 9.1,11.1 | 9.1,11.1 v9.1,11.3 | 9.1,11.1 v9.1,11.3 | v9.5,4.1 9.1,4.5 9.1,11.1
VCC5.0  (via drill 0.3, 0.6)
  Top 0.2: 16.32,14.97 IC3.20 | v16.6,14.7 16.32,14.97 | v16.6,14.7 16.32,14.97 | v16.6,14.7 17.4,13.9 17.4,7.4 17.6,7.4 17.8,7.2 17.8,7.25 | TP2.TP 14.82,0.48 14.8,0.5 14.1,1.2 13.75,1.2
  Top 0.5: 17.8,7.25 17.85,7.25 | 17.8,7.25 IC4.1 | 17.85,7.25 18,7.1 18,5.5 17.9,5.4 17.85,5.35 IC4.3 | v13.7,1.2 12,1.2 12,1.7 L2.2 11.5,2.51 11.5,4 11.3,4.04 C20.1 11.06,4.5 11,4.5 11,6.51 C19.+ 11.1,6.6 11.1,7.4 11.7,8 15.2,8 15.7,7.5 15.9,7.3 16.05,7.25 17.8,7.25 | v13.7,1.2 13.75,1.2 v13.7,1.2 | 17.8,7.25 17.85,7.25
  Bottom 0.2: v16.6,14.7 16.6,14.2 17,13.8 17.6,13.8 C14.2 | R11.2 4.05,8.55 4.1,8.5 4.11,8.51 R10.2 5.05,8.55 6.3,7.3 6.3,4.7 9.8,1.2 v13.7,1.2
  Bottom 0.5: CON2.16 52.18,0.3 44,0.3 40,4.3 37.9,4.3 33.9,0.3 14.6,0.3 v13.7,1.2
VDD3.3  (via drill 0.3)
  Top 0.2: IC1.24 33.54,8.65 v34.1,8.07 | IC1.36 40.56,13.2 v40.6,13.3 | IC1.48 35.7,18.6 35.7,18 35.2,17.5 v35.2,17.1 | v42.4,25.4 50.2,25.4 52.8,22.8 52.8,21.6 51.2,20 v48.1,20 | v50,16 50,15.9 50.5,15.4 50.5,15.3 50.5,15.2 v50.5,13.75 v50.5,7.2 | v31.7,24.7 29,24.7 L1.2 28.3,24.4 v26.1,24.4 v24.2,24.4 24.1,24.4 23.9,24.6 v18.9,24.6 | v8.4,27.2 6.6,27.2 | R8.1 40.04,6.06 40.04,6.8 36.3,6.8 v35.7,6.2 | 25.7,5.4 25.7,7 C1.+ 25.63,7.07 25,7.7 25,8 24.6,8.4 21.1,8.4 v20.7,8 | 25.7,5.4 25.7,4.41 C13.2 26.45,3.55 26.5,3.6 26.77,3.33 IC2.6 29.54,3.33 29.6,3.4 | 25.7,5.4 v24.5,5.4 | v20.1,14.3 20.5,14.7 v20.5,19.4
  Top 0.254: LED1.A 6.26,26.93 6.3,26.9 6.6,27.2
  Bottom 0.2: v40.6,13.3 41.8,13.3 41.8,12.93 C3.1 42.16,12.86 43.05,13.75 v50.5,13.75 | v35.2,17.1 35.2,18.1 37.4,20.3 37.4,20.7 | 37.4,20.7 C4.1 37.39,20.71 37.3,20.8 | 37.3,20.8 37.4,20.7 | v48.1,20 48.1,17.9 v50,16 | C2.1 33.5,8.7 v34.1,8.07 34.1,6.7 34.1,6 | R5.2 23.01,24.39 24,24.39 | D1.1 27.41,24.39 27.4,24.4 v26.1,24.4 | v31.7,24.7 35.9,24.7 37.3,23.3 | D2.3 22.1,20.7 23.2,20.7 24,21.5 24,24.3 24,24.39 | D2.3 | 24,24.39 v24.19,24.39 v24.2,24.4 | 34.1,6 35.5,6 v35.7,6.2 35.9,6.4 41.3,6.4 43.7,4 47.3,4 v50.5,7.2 | 13.8,26.8 13.74,26.86 R2.2 | 13.8,26.8 13.75,26.85 R1.2 11.25,26.85 10.8,27.3 8.5,27.3 v8.4,27.2 | 13.8,26.8 14.1,26.8 16.3,24.6 v18.9,24.6 | 29.6,3.4 31.5,3.4 34.1,6 | 26.4,3.4 29.6,3.4 | 25.9,3.9 26.4,3.4 | R9.1 25.77,4.87 25.8,4.9 25.9,4.8 25.9,3.9 | R1!.1 19.19,8.39 19.2,8.4 19.6,8 v20.7,8 | 26.4,3.4 29.6,3.4 | 25.9,3.9 26.4,3.4 | 25.9,3.9 25.9,4.6 25.1,5.4 v24.5,5.4 | v20.5,19.4 20.8,19.5 21.6,19.5 22.1,20 D2.3 | 19.4,8.4 19.4,11 19.9,11.5 19.9,14.1 v20.1,14.3 | 37.3,23.3 40.1,23.3 42.2,25.4 v42.4,25.4 | 37.3,23.3 37.3,20.8
VDDA  (via drill 0.3)
  Top 0.2: IC1.9 31.32,15.9 31.8,15.9 34.5,18.6 34.5,22.2 33.45,23.25 C7.+ 33.43,24.33 33.4,24.3 32.5,25.2 31.8,25.9 31.1,25.9 31,26.08 TP4.TP 31,26.26 v31,27.4 29.5,27.4 L1.1
  Bottom 0.2: C6.1 29.77,27.4 v31,27.4
VDDIO  (via drill 0.3)
  Top 0.2: IC3.17 16.12,16.93 v16.6,17.4 | IC3.4 20.27,11.72 17.3,14.7 17.3,15.5 | 17.3,15.5 17.3,16.7 v16.6,17.4 | IC3.19 15.97,15.62 16.1,15.5 17.3,15.5 | TP1.TP 15.42,19.98 16.6,18.8 16.6,17.5 16.5,17.4 v16.6,17.4
  Bottom 0.2: C18.1 18.01,17.29 18,17.3 17.9,17.4 v16.6,17.4
WP/  (via drill 0.3)
  Top 0.2: IC2.5 29.23,5.47 v29.2,5.5
  Bottom 0.2: R9.2 27.4,4.9 | R9.2 | v29.2,5.5 28,5.5 27.4,4.9 | R9.2 27.4,4.9 | R2!.1 27.44,4.94 27.4,4.9
(copper drawn outside any net)
  shapes: Top area x2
